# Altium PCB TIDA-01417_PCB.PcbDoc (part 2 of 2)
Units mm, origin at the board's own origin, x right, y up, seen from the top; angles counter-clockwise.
Board outline 64 x 64 mm, 2 copper layers (Top Layer, Bottom Layer), stack 1.575 mm thick; 69 components, 44 nets, 174 pads, 84 vias.
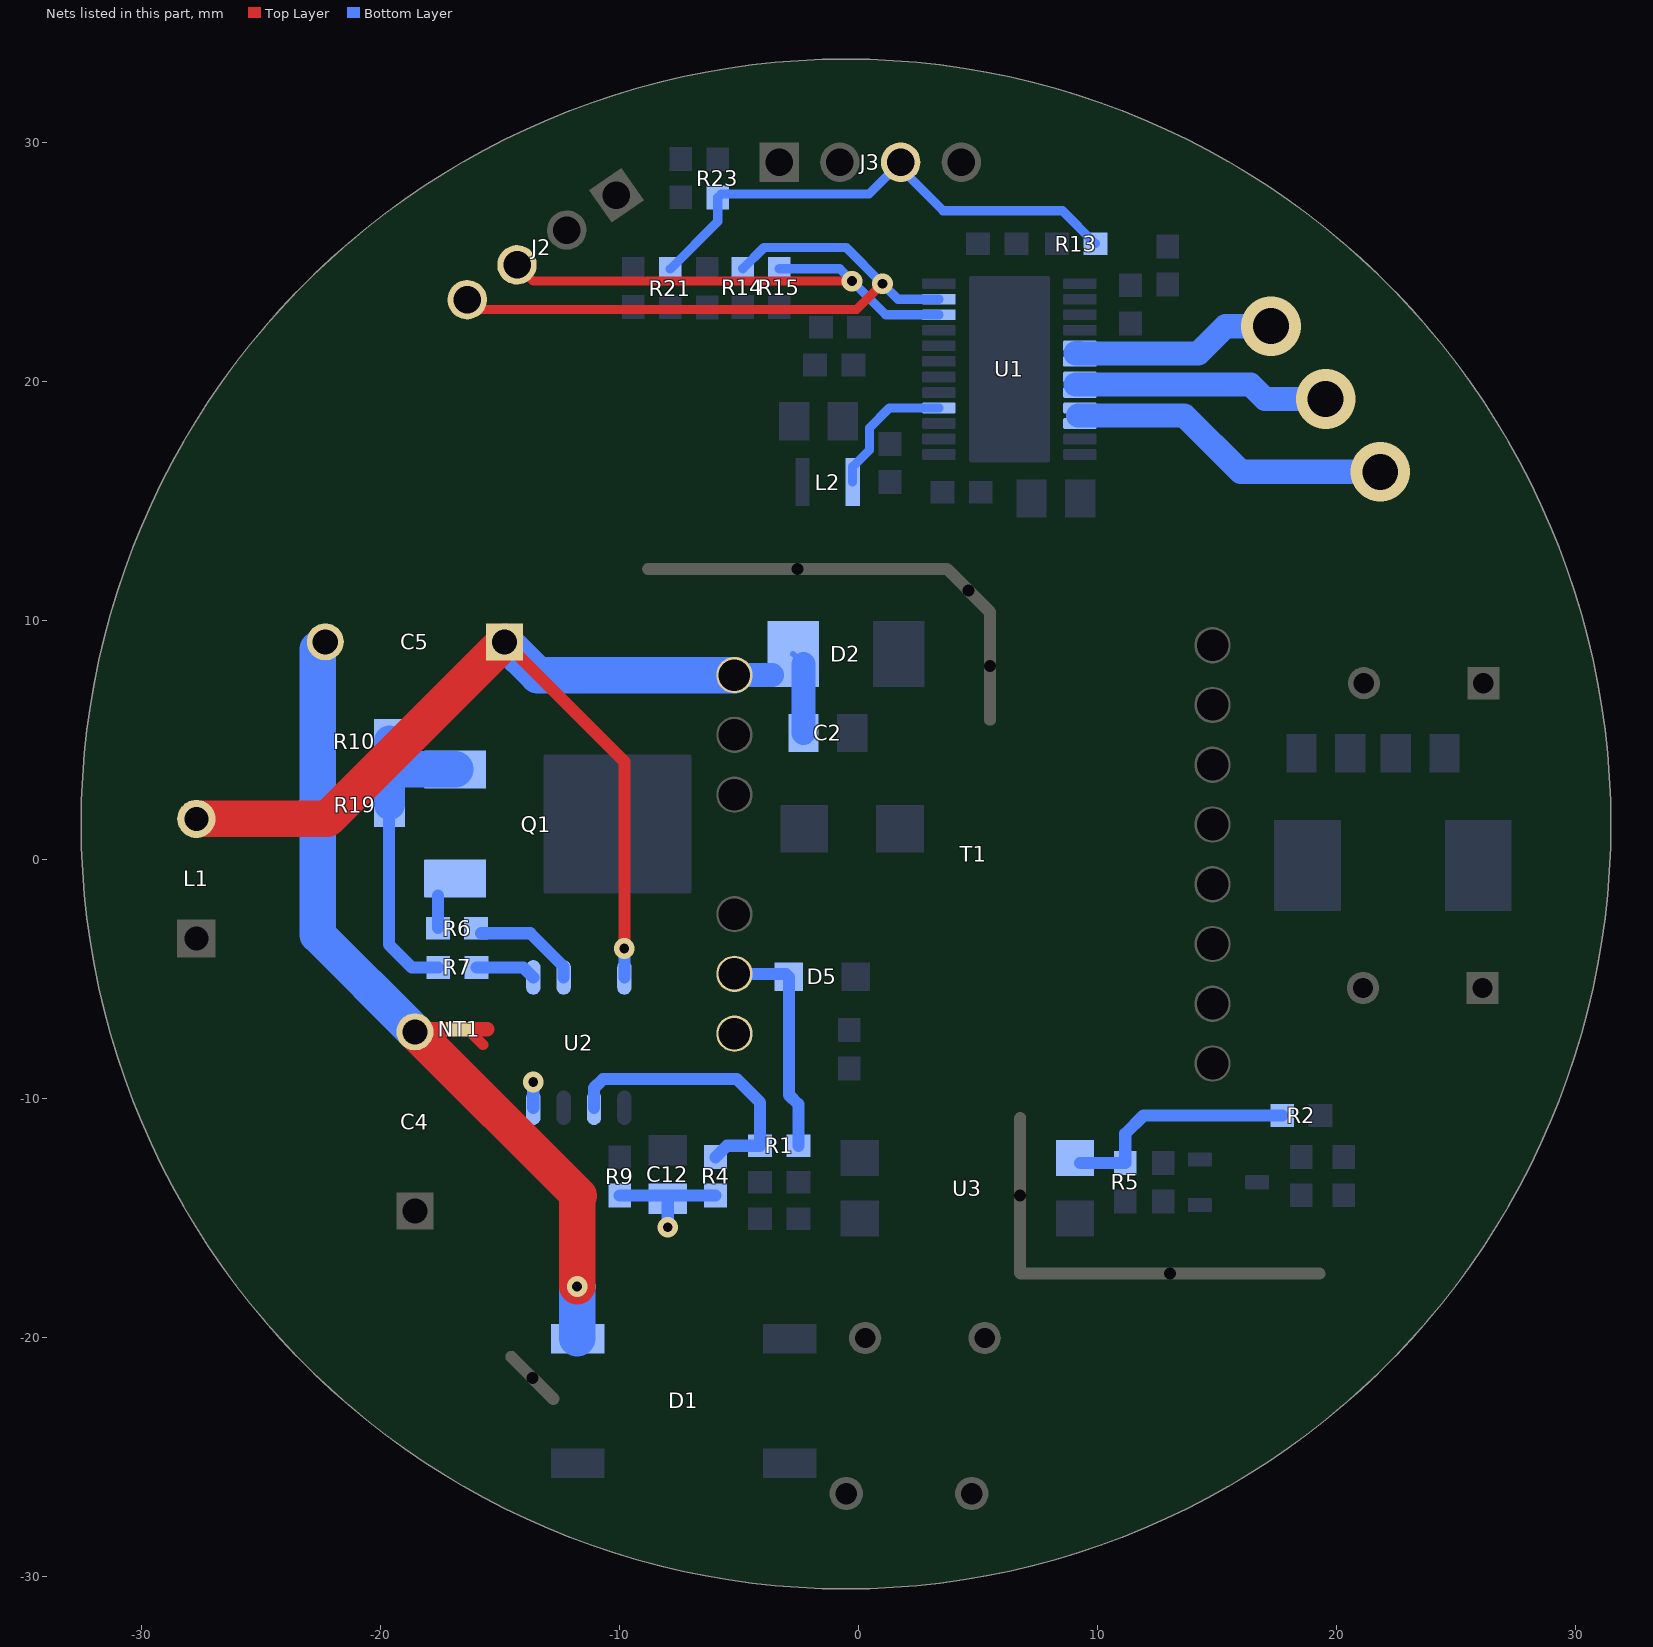
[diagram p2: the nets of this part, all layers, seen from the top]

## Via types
v1: diameter 0.864, hole 0.406, Top Layer to Bottom Layer, 58 vias
v2: diameter 0.5, hole 0.2, Top Layer to Bottom Layer, 15 vias
v3: diameter 0.5, hole 0.2, Top Layer to Bottom Layer, tented both sides, 6 vias
v4: diameter 2.5, hole 1.5, Top Layer to Bottom Layer, 5 vias

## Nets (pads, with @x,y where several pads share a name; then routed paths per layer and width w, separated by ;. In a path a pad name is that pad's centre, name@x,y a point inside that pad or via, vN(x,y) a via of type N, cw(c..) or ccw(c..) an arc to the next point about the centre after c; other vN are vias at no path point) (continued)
NetD5_2: D5.2 R1.2 T1.5 | length 9.7
  Bottom Layer w0.508: T1.5@-5.508,-4.784 T1.5@-5.174,-4.784 D5.2@-3.025,-4.784 ; D5.2@-2.89,-4.919 -2.89,-9.848 -2.502,-10.236 R1.2@-2.502,-11.976
NetL2_1: L2.1 U1.4 | length 5.8
  Bottom Layer w0.381: L2.1@-0.23,15.789 -0.23,16.431 0.468,17.128 0.468,18.049 1.31,18.89 U1.4@3.38,18.89
NetQ1_1: Q1.1 R6.2 | length 1.4
  Bottom Layer w0.508: R6.2@-17.58,-2.872 Q1.1@-17.58,-1.512
NetQ1_3: Q1.3 R7.2 R10.2 R19.2 | length 13.5
  Bottom Layer w0.508: R19.2@-19.632,2.31 -19.632,-3.557 -18.674,-4.515 R7.2@-17.565,-4.515
  Bottom Layer w1.3: R19.2@-19.606,2.31 R10.2@-19.606,4.957
  Bottom Layer w1.524: -19.361,3.771 Q1.3@-16.851,3.771
NetR1_1: R1.1 R4.2 U2.2 | length 12.2
  Bottom Layer w0.508: U2.2@-11.049,-10.383 -11.049,-9.563 -10.668,-9.182 -5.08,-9.182 -4.102,-10.16 R1.1@-4.102,-11.976 -5.488,-11.976 R4.2@-5.964,-12.453
NetR2_1: R2.1 R5.2 U3.1 | length 10
  Bottom Layer w0.508: U3.1@9.288,-12.7 R5.2@11.176,-12.7 11.176,-11.468 11.938,-10.706 R2.1@17.742,-10.706
NetR6_1: R6.1 U2.6 | length 4.5
  Bottom Layer w0.508: R6.1@-15.766,-3.086 -13.716,-3.086 -12.319,-4.483 U2.6@-12.319,-4.933
NetR7_1: R7.1 U2.5 | length 2.5
  Bottom Layer w0.508: R7.1@-15.965,-4.515 -14.007,-4.515 U2.5@-13.589,-4.933
PGND: C4.2 C5.2 D1.2 NT1.2 R10.1 R19.1 | length 34.9
  Top Layer w0.25: C4.2@-18.542,-7.21 C4.2@-18.534,-7.218
  Top Layer w0.6: C4.2@-18.42,-7.104 NT1.2@-16.935,-7.104
  Top Layer w1.524: C4.2@-18.534,-7.218 -11.684,-14.068 -11.758,-14.143 v1(-11.758,-17.86)
  Bottom Layer w1.524: C5.2@-22.606,8.792 -22.606,-3.146 C4.2@-18.542,-7.21 ; D1.2@-11.758,-20.022 v1(-11.758,-17.86)
SCL: J2.3 R15.2 U1.10 | length 21.8
  Top Layer w0.381: J2.3@-14.271,24.877 -13.594,24.199 v1(-0.254,24.199)
  Bottom Layer w0.381: R15.2@-3.302,24.714 -0.769,24.714 v1(-0.254,24.199) 1.155,22.79 U1.10@3.38,22.79
SDA: J2.4 R14.2 U1.11 | length 26.9
  Top Layer w0.381: J2.4@-15.937,23.005 -0.071,23.005 v1(1.016,24.092)
  Bottom Layer w0.381: R14.2@-4.826,24.714 -4.826,24.718 -3.939,25.605 -0.497,25.605 v1(1.016,24.092) 1.667,23.44 U1.11@3.38,23.44
SGND: C12.1 NT1.1 R4.1 R9.1 T1.6 U2.4 | length 7.9
  Top Layer w0.2: NT1.1@-16.229,-7.39 -16.166,-7.453 ; NT1.1@-16.229,-7.22 NT1.1@-16.144,-7.305
  Top Layer w0.45: -16.081,-7.368 -15.697,-7.751
  Top Layer w0.508: v1@-7.974,-15.393 v1(-7.965,-15.383)
  Top Layer w0.6: NT1.1@-16.427,-7.104 -15.519,-7.104
  Bottom Layer w0.508: U2.4@-13.589,-10.383 v1(-13.589,-9.309) ; R9.1@-9.974,-14.054 R4.1@-5.966,-14.054 ; v1(-7.965,-15.383) C12.1@-7.965,-14.192
SPEED: J3.3 R13.1 R21.1 R23.2 | length 21.5
  Bottom Layer w0.381: R21.1@-7.863,24.702 -5.875,26.69 R23.2@-5.875,27.69 -5.726,27.84 0.446,27.84 J3.3@1.778,29.172 ; J3.3@1.778,28.918 3.556,27.14 8.549,27.14 R13.1@9.924,25.765
U: U1.17 U1.18 | length 8.6
  Bottom Layer w1.016: 9.099,21.176 9.279,21.175 ; 9.28,21.175 13.595,21.171 14.224,21.171 15.367,22.314 v4(17.272,22.314)
V: U1.19 U1.20 | length 10.7
  Bottom Layer w1.016: 9.104,19.872 16.412,19.872 17.018,19.266 v4(19.558,19.266)
VDCBUS: C2.1 C5.1 D2.2 L1.2 T1.1 U2.8 | length 47.3
  Top Layer w0.508: C5.1@-14.792,9.106 -9.779,4.093 v1(-9.779,-3.721)
  Top Layer w1.524: L1.2@-27.686,1.7 -22.198,1.7 C5.1@-14.792,9.106
  Bottom Layer w0.254: D2.2@-2.718,8.598 D2.2@-2.286,8.166
  Bottom Layer w0.508: U2.8@-9.779,-4.933 v1(-9.779,-3.721)
  Bottom Layer w1.016: T1.1@-5.174,7.716 D2.2@-3.6,7.716 ; C2.1@-2.286,5.296 D2.2@-2.286,8.166
  Bottom Layer w1.524: C5.1@-14.792,9.106 -13.402,7.716 T1.1@-5.174,7.716
W: U1.21 U1.22 | length 13.6
  Bottom Layer w1.016: 9.203,18.573 13.647,18.573 16.003,16.218 v4(21.844,16.218)
pads on no net: T1.2 T1.4 T1.7 T1.10 T1.11 T1.14 U1.25@6.329,20.515

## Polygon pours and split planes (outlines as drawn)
GND on Bottom Layer "Bottom Layer-No Net 3" (solid, remove dead copper, pour order 12): -22.352,24.6 -17.272,19.52 -9.652,19.52 -3.297,13.165 4.323,13.165 5.588,11.9 10.668,11.9 13.208,9.36 13.208,-8.42 10.668,-10.96 10.668,-15.732 28.756,-15.732 33.528,-10.96 33.528,11.9 10.668,34.76 -12.192,34.76
NetC17_1 on Bottom Layer "Bottom Layer-No Net" (solid, pour order 4): 13.97,-2.578 13.462,-3.086 13.462,-6.642 13.716,-6.896 13.97,-7.15 16.002,-7.15 16.256,-6.896 16.256,-5.88 19.812,-2.324 20.32,-2.324 20.828,-1.816 20.828,2.502 20.574,2.756 17.272,2.756 16.764,2.248 16.51,1.994 16.51,-1.562 15.494,-2.578
NetC2_2 on Bottom Layer "Top Layer-No Net" (solid, remove dead copper, pour order 2): -0.889,6.185 -0.889,4.534 -0.889,4.153 0.254,4.153 0.457,3.95 0.457,0.648 0.686,0.419 3.302,0.419 4.343,1.461 4.572,1.689 4.572,9.842 4.166,10.249 1.702,10.249 0.889,10.249 0.635,9.995 0.635,8.522 0.635,6.617 0.203,6.185
+24V on Bottom Layer "Bottom Layer-No Net 1" (solid, pour order 8): 23.876,6.82 25.4,8.344 29.718,8.344 30.988,7.074 30.988,0.978 30.988,-3.848 29.718,-5.118 29.718,-5.372 29.718,-6.134 29.21,-6.642 28.702,-7.15 25.146,-7.15 23.876,-5.88 23.876,6.82
PGND on Bottom Layer "BOTTOM_LAYER_PGND_P024" (solid, remove dead copper, pour order 24): -19.05,-6.096 -18.034,-6.096 -17.526,-6.604 -17.526,-7.62 -17.526,-7.874 -18.034,-8.382 -18.796,-8.382 -19.05,-8.382 -19.558,-7.874 -19.558,-6.604 -19.05,-6.096
SGND on Top Layer "Top Layer-No Net 4" (solid, pour order 22): -6.096,-5.838 1.27,-5.838 1.27,-15.532 0.762,-16.04 -8.006,-16.04 -16.463,-7.583 -16.463,-6.807 -13.236,-6.807 -11.311,-8.928 -7.112,-8.928 -6.096,-7.912
GND on Top Layer "Top Layer-No Net 3" (solid, pour order 18): -22.352,24.6 -17.272,19.52 -9.652,19.52 -3.266,13.134 4.354,13.134 5.588,11.9 10.668,11.9 13.208,9.36 13.208,9.331 13.208,-8.166 10.668,-10.706 10.668,-15.788 26.668,-15.788 32.766,-9.69 33.528,-8.928 33.528,9.36 33.528,14.44 20.828,27.14 14.478,33.49 -9.652,33.49 -13.462,33.49
+24V on Top Layer "Top Layer-No Net 2" (solid, pour order 16): 23.876,6.82 25.4,8.344 28.94,8.344 31.496,8.344 30.734,7.582 30.734,-7.15 25.146,-7.15 23.876,-5.88 23.876,6.82
NetC17_1 on Top Layer "Top Layer-No Net 1" (solid, pour order 14): 13.462,-3.086 13.97,-2.578 15.494,-2.578 16.51,-1.562 16.51,1.994 17.272,2.756 20.574,2.756 20.828,2.502 20.828,-1.816 20.32,-2.324 19.812,-2.324 16.256,-5.88 16.256,-6.896 16.027,-7.125 13.945,-7.125 13.462,-6.642 13.462,-3.086
PGND on Top Layer "TOP_LAYER_PGND_P030" (solid, remove dead copper, pour order 30): -18.034,-6.096 -17.526,-6.604 -17.526,-7.874 -18.034,-8.382 -19.05,-8.382 -19.558,-7.874 -19.558,-6.858 -19.558,-6.604 -19.05,-6.096 -18.034,-6.096

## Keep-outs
Keep-Out Layer:
  circle w0.254: c-0.508,1.494 r32.064
  text ".Layer_Name" at -35.636,-60.706 h1.52

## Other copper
Top Layer:
  text ".Layer_Name" at -35.636,-60.706 h1.52
Bottom Layer:
  text ".Layer_Name" at -35.636,-60.706 h1.52

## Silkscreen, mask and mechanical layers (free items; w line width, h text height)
Top Overlay:
  text "GND" at -12.402,30.461 h0.76 r305
  text "FG" at -14.094,28.51 h0.76 r305
  text "SCL" at -16.587,27.541 h0.76 r305
  text "GND" at -3.81,27.432 h0.76 r270
  text "FG" at -1.27,27.432 h0.76 r270
  text "SPEED" at 1.27,27.432 h0.76 r270
  text "DIR" at 3.996,27.366 h0.76 r270
  text "SDA" at -18.693,26.146 h0.76 r305
  text "W   V   U" at 21.082,13.716 h3 r127
  text "TIDA-01417" at -7.142,-14.464 h2.75
  text "N" at 15.543,-20.563 h3 r90
  text "L" at 10.308,-23.461 h3 r90
  text ".Layer_Name" at -35.636,-60.706 h1.52
Bottom Overlay:
  text ".Layer_Name" at -35.636,-60.706 h1.52
Top Paste:
  text ".Layer_Name" at -35.636,-60.706 h1.52
Bottom Paste:
  text ".Layer_Name" at -35.636,-60.706 h1.52
Top Solder:
  text ".Layer_Name" at -35.636,-60.706 h1.52
  text ".Layer_Name" at -35.636,-60.706 h1.52
Bottom Solder:
  text ".Layer_Name" at -35.636,-60.706 h1.52
Drill Guide:
  text ".Layer_Name" at -35.636,-60.706 h1.52
M3 3D STEP Top:
  text ".Layer_Name" at -35.636,-60.706 h1.52
M4 3D STEP Bottom:
  text ".Layer_Name" at -35.636,-60.706 h1.52
M5 Assembly Top:
  lines w0.254: -57.709,-62.526 109.931,-62.526 ; -57.709,-57.362 109.982,-57.362 ; -57.709,-52.197 -57.709,-67.691 44.018,-67.691 109.982,-67.691 109.982,-52.197 -57.696,-52.197 -57.696,-67.691 -17.678,-67.691 ; 4.902,-67.691 4.902,-52.197 ; 37.084,-57.362 37.084,-52.197 ; 58.42,-57.362 58.42,-52.197 ; 74.219,-67.856 74.219,-62.704
  text "COMPONENTS MARKED 'DNP' SHOULD NOT BE POPULATED." at -20.993,-46.99 h1.52
  text "ASSEMBLY VARIANT:" at -21.006,-49.924 h1.52
  text ".VariantName" at 5.309,-49.924 h1.52
  text "PCB VIEWED FROM TOP SIDE" at -56.096,-55.554 h1.52
  text "BOARD #:" at 6.807,-55.554 h1.52
  text ".PRJ_Number" at 20.663,-55.554 h1.52
  text "REV:" at 42.113,-55.554 h1.52
  text ".PCB_Rev" at 49.517,-55.554 h1.52
  text "SVN REV:" at 63.398,-55.554 h1.52
  text ".VersionControl_RevNumber" at 76.251,-55.554 h1.52
  text "TID #:" at 6.807,-60.719 h1.52
  text ".TID" at 20.663,-60.719 h1.52
  text "PLOT NAME =" at -56.096,-65.934 h1.52
  text ".plot_File_Name" at -35.636,-65.934 h1.52
  text "GENERATED    :" at 6.858,-65.934 h1.52
  text ".Print_Date" at 28.943,-65.934 h1.52
  text ".Print_Time" at 47.46,-65.934 h1.52
  text "TEXAS INSTRUMENTS" at 79.578,-65.934 h1.52
M6 Assembly Bottom:
  lines w0.254: -57.721,-57.374 109.969,-57.374 ; -57.671,-62.539 109.969,-62.539 ; -21.958,-67.869 -21.958,-62.717 ; -6.159,-57.374 -6.159,-52.21 ; 15.176,-57.374 15.176,-52.21 ; 47.358,-67.704 47.358,-52.21 ; 69.939,-67.704 109.957,-67.704 109.957,-52.21 -57.721,-52.21 -57.721,-67.704 8.242,-67.704 109.969,-67.704 109.969,-52.21
  text "COMPONENTS MARKED 'DNP' SHOULD NOT BE POPULATED." at 104.699,-46.977 h1.52
  text ".VariantName" at 78.181,-49.924 h1.52
  text "ASSEMBLY VARIANT:" at 104.572,-49.924 h1.52
  text ".VersionControl_RevNumber" at -23.99,-55.567 h1.52
  text "SVN REV:" at -11.138,-55.567 h1.52
  text ".PCB_Rev" at 2.743,-55.567 h1.52
  text "REV:" at 10.147,-55.567 h1.52
  text ".PRJ_Number" at 31.598,-55.567 h1.52
  text "BOARD #:" at 45.453,-55.567 h1.52
  text "PCB VIEWED FROM BOTTOM SIDE" at 108.356,-55.567 h1.52
  text ".TID" at 31.598,-60.731 h1.52
  text "TID #:" at 45.453,-60.731 h1.52
  text "TEXAS INSTRUMENTS" at -27.318,-65.947 h1.52
  text ".Print_Time" at 4.801,-65.947 h1.52
  text ".Print_Date" at 23.317,-65.947 h1.52
  text "GENERATED    :" at 45.402,-65.947 h1.52
  text ".plot_File_Name" at 87.897,-65.947 h1.52
  text "PLOT NAME =" at 108.356,-65.947 h1.52
M9 Title Sheet:
  drawing of 57 lines, arcs and shapes, not listed
  text "1" at -31.5,165.227 h1.78
  text "2" at 31.89,165.227 h1.78
  text "3" at 95.119,165.227 h1.78
  text "4" at 158.788,165.227 h1.78
  text "5" at 222.263,165.227 h1.78
  text "6" at 285.89,165.227 h1.78
  text "A" at -60.871,136.195 h1.78
  text "A" at 315.049,136.195 h1.78
  text "B" at -60.871,75.743 h1.78
  text "B" at 315.049,75.743 h1.78
  text "C" at -60.871,15.418 h1.78
  text "C" at 315.049,15.418 h1.78
  text "PROJECT TITLE:" at 237.833,-31.852 h1.14
  text ".PRJ_Title" at 239.103,-35.238 h1.78
  text "DESIGNED FOR:" at 237.833,-39.497 h1.14
  text ".PRJ_Customer" at 239.103,-43.053 h1.78
  text "D" at -60.871,-44.78 h1.78
  text "D" at 315.049,-44.78 h1.78
  text "FILE NAME:" at 237.833,-47.117 h1.14
  text ".PCB_File_Name_No_Path" at 239.103,-50.165 h1.78
  text "Texas Instruments (TI) and/or its licensors do not warrant the accuracy or completeness of this specification" at 111.608,-54.276 h1.14
  text "ENGINEER:" at 237.833,-54.483 h1.14
  text "LAYOUT BY:" at 276.06,-54.483 h1.14
  text "or any information contained therein. TI and/or its licensors do not warrant that this design will meet" at 110.465,-57.137 h1.14
  text ".PRJ_Engineer" at 239.103,-58.42 h1.78
  text ".PCB_Layout" at 277.343,-58.42 h1.78
  text "the specifications, will be suitable for your application or fit for any particular purpose, or will operate in" at 110.465,-59.999 h1.14
  text ".Layer_Name" at -35.636,-60.706 h1.52
  text "ALTIUM DESIGNER VERSION:" at 276.06,-62.357 h1.14
  text "an implementation. TI and/or its licensors do not warrant that the design is production worthy. You should" at 110.465,-62.861 h1.14
  text "completely validate and test your design implementation to confirm the system functionality for your application." at 111.608,-65.722 h1.14
  text ".print_Scale" at 239.103,-65.744 h1.78
  text ".Application_BuildNumber" at 277.343,-65.744 h1.78
  text "1" at -31.5,-70.993 h1.78
  text "2" at 31.89,-70.993 h1.78
  text "3" at 95.119,-70.993 h1.78
  text "4" at 158.788,-70.993 h1.78
  text "5" at 222.263,-70.993 h1.78
  text "6" at 285.89,-70.993 h1.78
M10 Fab Notes:
  drawing of 173 lines, arcs and shapes, not listed
  text "DESIGN INFORMATION" at 264.11,118.605 h1.52
  text "MIN. TRACK WIDTH:" at 247.738,114.033 h1.52
  text "8" at 275.582,114.033 h1.52
  text "MIL" at 279.513,114.033 h1.52
  text "MIN. CLEARANCE:" at 247.738,110.681 h1.52
  text "0.2" at 274.058,110.681 h1.52
  text "mm" at 279.513,110.681 h1.52
  text "MIN. VIA PAD SIZE:" at 247.738,107.328 h1.52
  text "24" at 274.821,107.328 h1.52
  text "MIL" at 279.513,107.328 h1.52
  text "0.05mm (2MIL)" at 265.391,103.728 h1.52
  text "MINIMUM ANNULAR RING" at 239.375,103.619 h1.52
  text "EXTERNAL" at 283.374,103.619 h1.52
  text "PER" at 244.455,100.622 h1.52
  text "IPC-D-275 CLASS 2 LEVEL C" at 250.043,100.622 h1.52
  text "MIL, HOLES" at 287.844,97.77 h1.52
  text "+/-" at 277.876,97.752 h1.52
  text "+/-" at 299.568,97.752 h1.52
  text "REGISTRATION TOLERANCES:" at 239.375,97.625 h1.52
  text "METAL" at 269.85,97.625 h1.52
  text "5" at 284.485,97.625 h1.52
  text "3" at 305.643,97.625 h1.52
  text "MIL" at 308.596,97.625 h1.52
  text "+/-" at 299.568,94.755 h1.52
  text "HOLE SIZE TOLERANCE (UNLESS OTHERWISE SPECIFIED):" at 239.375,94.628 h1.52
  text "3" at 305.643,94.628 h1.52
  text "MIL" at 308.596,94.628 h1.52
  text "MATERIAL:" at 237.476,89.307 h1.52
  text "FR-4 High Tg" at 262.532,85.743 h1.52
  text "FR-408" at 248.17,85.525 h1.52
  text "OTHER" at 285.965,85.525 h1.52
  text "X" at 258.597,85.433 h1.52
  text "62 MIL (1.6mm) +/-10%" at 256.3,81.392 h1.52
  text "THICKNESS:" at 239.375,81.284 h1.52
  text "X" at 253.045,81.284 h1.52
  text "OTHER" at 288.937,81.284 h1.52
  text "TOLERANCE:" at 239.375,77.27 h1.52
  text "X" at 260.694,77.27 h1.52
  text "ANSI IPC-6012 TYPE 3 CLASS 2" at 265.442,77.27 h1.52
  text "OTHER +/-" at 265.442,73.308 h1.52
  text "BOW & TWIST:" at 239.375,69.32 h1.52
  text "X" at 260.694,69.32 h1.52
  text "ANSI IPC-6012 TYPE 3 CLASS 2" at 265.442,69.32 h1.52
  text "OTHER +/-" at 265.442,65.294 h1.52
  text "DRILLING:" at 237.476,61.776 h1.52
  text "REFERENCE:" at 239.375,58.805 h1.52
  text "X" at 255.84,58.805 h1.52
  text "AS SHOWN" at 260.59,58.805 h1.52
  text "X" at 278.726,58.805 h1.52
  text "NC_DRILL FILES" at 282.206,58.805 h1.52
  text "PTH COPPER THICKNESS:" at 239.375,54.791 h1.52
  text "X" at 268.083,54.791 h1.52
  text "20-30 um" at 271.563,54.791 h1.52
  text "OTHER" at 289.775,54.791 h1.52
  text "BOARD FINISH:" at 237.476,50.753 h1.52
  text "SILKSCREEN:" at 241.419,47.756 h1.52
  text "X" at 265.518,47.756 h1.52
  text "TOP" at 268.718,47.756 h1.52
  text "X" at 278.472,47.756 h1.52
  text "BOTTOM" at 281.698,47.756 h1.52
  text "SILKSCREEN COLOR:" at 241.419,43.514 h1.52
  text "X" at 265.491,43.514 h1.52
  text "WHITE" at 268.718,43.514 h1.52
  text "OTHER" at 281.698,43.514 h1.52
  text "X" at 268.819,39.47 h1.52
  text "GREEN" at 272.046,39.47 h1.52
  text "OTHER" at 287.743,39.47 h1.52
  text "SOLDER RESIST COLOR:" at 241.419,39.196 h1.52
  text "X" at 268.819,35.152 h1.52
  text "MATTE" at 272.046,35.152 h1.52
  text "SEMI-GLOSS" at 287.731,35.136 h1.52
  text "IMMERSION GOLD (ENIG)" at 264.426,30.364 h1.52
  text "ENEPIG" at 298.399,30.28 h1.52
  text "SURFACE FINISH:" at 237.476,30.255 h1.52
  text "X" at 259.677,30.255 h1.52
  text "IMM. TIN/SILVER OR EQUIV" at 245.847,26.267 h1.52
  text "OTHER" at 282.206,26.267 h1.52
  text "ARRAY/PANEL:" at 237.476,21.721 h1.52
  text "CUT AND TRIM PER M1 BOARD OUTLINE" at 264.426,21.612 h1.52
  text "N.C. ROUTE" at 264.426,17.758 h1.52
  text "X" at 281.672,17.758 h1.52
  text "V. SCORE" at 286.422,17.758 h1.52
  text "CERTIFICATION:" at 237.476,14.278 h1.52
  text "MATERIALS AND WORKMANSHIP FOR ALL PCBS" at 255.891,14.278 h1.52
  text "TO MEET OR EXCEED THE REQUIREMENTS OF:" at 255.891,11.789 h1.52
  text "X" at 246.404,8.322 h1.52
  text "ANSI IPC-A-600F CLASS ->" at 249.935,8.322 h1.52
  text "X" at 291.567,8.322 h1.52
  text "2" at 294.588,8.322 h1.52
  text "1" at 286.587,8.284 h1.52
  text "3" at 303.58,8.284 h1.52
  text "X" at 267.081,4.271 h1.52
  text "RoHS" at 270.56,4.271 h1.52
  text "OTHER" at 286.928,4.271 h1.52
  text "PER ORDER" at 297.013,4.271 h1.52
  text "ALL BOARDS MUST MEET OR EXCEED UL94-V0 REQUIREMENTS." at 238.176,0.064 h1.52
  text "PCB MUST BEAR THE UL94V-0 UL REGISTERED MATERIAL ID NUMBER" at 238.176,-2.984 h1.52
  text "ADDITIONAL REQUIREMENTS:" at 237.476,-7.388 h1.52
  text "MICROSECTION:" at 239.375,-10.309 h1.52
  text "YES" at 262.381,-10.309 h1.52
  text "REQUIRED" at 284.263,-14.275 h1.52
  text "BARE BOARD ELEC. TEST:" at 239.375,-14.347 h1.52
  text "NONE" at 272.541,-14.347 h1.52
  text "X" at 281.037,-14.347 h1.52
  text "PER ORDER" at 299.3,-14.347 h1.52
  text ".Layer_Name" at -35.636,-60.706 h1.52
M11 Gerber Information:
  lines w0.254: -57.709,-62.526 109.931,-62.526 ; -57.709,-57.362 109.982,-57.362 ; -57.709,-52.197 -57.709,-67.691 44.018,-67.691 109.982,-67.691 109.982,-52.197 -57.696,-52.197 -57.696,-67.691 -17.678,-67.691 ; 4.902,-67.691 4.902,-52.197 ; 37.084,-57.362 37.084,-52.197 ; 58.42,-57.362 58.42,-52.197 ; 74.219,-67.856 74.219,-62.704
  text "ALL ARTWORK VIEWED FROM TOP SIDE" at -56.096,-55.554 h1.52
  text "BOARD #:" at 6.807,-55.554 h1.52
  text ".PRJ_Number" at 20.663,-55.554 h1.52
  text "REV:" at 42.113,-55.554 h1.52
  text ".PCB_Rev" at 49.517,-55.554 h1.52
  text "SVN REV:" at 63.398,-55.554 h1.52
  text ".VersionControl_RevNumber" at 76.251,-55.554 h1.52
  text "LAYER NAME =" at -56.096,-60.706 h1.52
  text "TID #:" at 6.807,-60.719 h1.52
  text ".TID" at 20.663,-60.719 h1.52
  text "PLOT NAME =" at -56.096,-65.934 h1.52
  text ".plot_File_Name" at -35.636,-65.934 h1.52
  text "GENERATED    :" at 6.858,-65.934 h1.52
  text ".Print_Date" at 28.943,-65.934 h1.52
  text ".Print_Time" at 47.46,-65.934 h1.52
  text "TEXAS INSTRUMENTS" at 79.578,-65.934 h1.52
M12 Stackup:
  drawing of 191 lines, arcs and shapes, not listed
  text "Layer" at 198.383,159.982 h1.52
  text "Name" at 208.794,159.982 h1.52
  text "Material" at 232.41,159.982 h1.52
  text "Thickness" at 254.248,159.982 h1.52
  text "Constant" at 270.754,159.982 h1.52
  text "Board Layer Stack" at 285.228,159.982 h1.52
  text "1" at 198.383,156.934 h1.52
  text "Top Overlay" at 208.794,156.934 h1.52
  text "2" at 198.383,153.886 h1.52
  text "Top Solder" at 208.794,153.886 h1.52
  text "Solder Resist" at 232.41,153.886 h1.52
  text "0.40mil" at 254.248,153.886 h1.52
  text "3.5" at 270.754,153.886 h1.52
  text "3" at 198.383,150.838 h1.52
  text "Top Layer" at 208.794,150.838 h1.52
  text "Copper" at 232.41,150.838 h1.52
  text "1.40mil" at 254.248,150.838 h1.52
  text "4" at 198.383,147.79 h1.52
  text "Dielectric1" at 208.794,147.79 h1.52
  text "FR-4" at 232.41,147.79 h1.52
  text "59.20mil" at 254.248,147.79 h1.52
  text "4.8" at 270.754,147.79 h1.52
  text "5" at 198.383,144.742 h1.52
  text "Bottom Layer" at 208.794,144.742 h1.52
  text "Copper" at 232.41,144.742 h1.52
  text "1.40mil" at 254.248,144.742 h1.52
  text "6" at 198.383,141.694 h1.52
  text "Bottom Solder" at 208.794,141.694 h1.52
  text "Solder Resist" at 232.41,141.694 h1.52
  text "0.40mil" at 254.248,141.694 h1.52
  text "3.5" at 270.754,141.694 h1.52
  text "7" at 198.383,138.646 h1.52
  text "Bottom Overlay" at 208.794,138.646 h1.52
  text ".Layer_Name" at -35.636,-60.706 h1.52
M13 Component Bodies Top:
  text ".Layer_Name" at -35.636,-60.706 h1.52
M14 Component Bodies Bottom:
  text ".Layer_Name" at -35.636,-60.706 h1.52
M15 Courtyards Top:
  text ".Layer_Name" at -35.636,-60.706 h1.52
M16 Courtyards Bottom:
  text ".Layer_Name" at -35.636,-60.706 h1.52
Drill Drawing:
  drawing of 156 lines, arcs and shapes, not listed
  text "Symbol" at 85.491,47.094 h1.83
  text "Quantity" at 92.749,47.094 h1.83
  text "Finished Hole Size" at 100.805,47.094 h1.83
  text "Plated" at 116.597,47.094 h1.83
  text "Hole Type" at 122.803,47.094 h1.83
  text "Drill Layer Pair" at 131.956,47.094 h1.83
  text "Hole Tolerance" at 149.977,47.094 h1.83
  text "21" at 92.749,44.563 h1.52
  text "7.87mil (0.200mm)" at 100.805,44.563 h1.52
  text "PTH" at 116.597,44.563 h1.52
  text "Round" at 122.803,44.563 h1.52
  text "Top Layer - Bottom Layer" at 131.956,44.563 h1.52
  text "58" at 92.749,42.033 h1.52
  text "16.00mil (0.406mm)" at 100.805,42.033 h1.52
  text "PTH" at 116.597,42.033 h1.52
  text "Round" at 122.803,42.033 h1.52
  text "Top Layer - Bottom Layer" at 131.956,42.033 h1.52
  text "6" at 92.749,39.503 h1.52
  text "33.46mil (0.850mm)" at 100.805,39.503 h1.52
  text "PTH" at 116.597,39.503 h1.52
  text "Round" at 122.803,39.503 h1.52
  text "Top Layer - Bottom Layer" at 131.956,39.503 h1.52
  text "2" at 92.749,36.972 h1.52
  text "35.43mil (0.900mm)" at 100.805,36.972 h1.52
  text "PTH" at 116.597,36.972 h1.52
  text "Round" at 122.803,36.972 h1.52
  text "Top Layer - Bottom Layer" at 131.956,36.972 h1.52
  text "2" at 92.749,34.442 h1.52
  text "39.37mil (1.000mm)" at 100.805,34.442 h1.52
  text "PTH" at 116.597,34.442 h1.52
  text "Round" at 122.803,34.442 h1.52
  text "Top Layer - Bottom Layer" at 131.956,34.442 h1.52
  text "4" at 92.749,31.911 h1.52
  text "41.34mil (1.050mm)" at 100.805,31.911 h1.52
  text "PTH" at 116.597,31.911 h1.52
  text "Round" at 122.803,31.911 h1.52
  text "Top Layer - Bottom Layer" at 131.956,31.911 h1.52
  text "8" at 92.749,29.381 h1.52
  text "45.28mil (1.150mm)" at 100.805,29.381 h1.52
  text "PTH" at 116.597,29.381 h1.52
  text "Round" at 122.803,29.381 h1.52
  text "Top Layer - Bottom Layer" at 131.956,29.381 h1.52
  text "14" at 92.749,26.851 h1.52
  text "51.97mil (1.320mm)" at 100.805,26.851 h1.52
  text "PTH" at 116.597,26.851 h1.52
  text "Round" at 122.803,26.851 h1.52
  text "Top Layer - Bottom Layer" at 131.956,26.851 h1.52
  text "5" at 92.749,24.32 h1.52
  text "59.06mil (1.500mm)" at 100.805,24.32 h1.52
  text "PTH" at 116.597,24.32 h1.52
  text "Round" at 122.803,24.32 h1.52
  text "Top Layer - Bottom Layer" at 131.956,24.32 h1.52
  text "2" at 92.749,21.79 h1.52
  text "20.00mil (0.508mm)" at 100.805,21.79 h1.52
  text "NPTH" at 116.597,21.79 h1.52
  text "Slot" at 122.803,21.79 h1.52
  text "Top Layer - Bottom Layer" at 131.956,21.79 h1.52
  text "1" at 92.749,19.259 h1.52
  text "20.00mil (0.508mm)" at 100.805,19.259 h1.52
  text "NPTH" at 116.597,19.259 h1.52
  text "Slot" at 122.803,19.259 h1.52
  text "Top Layer - Bottom Layer" at 131.956,19.259 h1.52
  text "1" at 92.749,16.729 h1.52
  text "20.00mil (0.508mm)" at 100.805,16.729 h1.52
  text "NPTH" at 116.597,16.729 h1.52
  text "Slot" at 122.803,16.729 h1.52
  text "Top Layer - Bottom Layer" at 131.956,16.729 h1.52
  text "2" at 92.749,14.198 h1.52
  text "20.00mil (0.508mm)" at 100.805,14.198 h1.52
  text "NPTH" at 116.597,14.198 h1.52
  text "Slot" at 122.803,14.198 h1.52
  text "Top Layer - Bottom Layer" at 131.956,14.198 h1.52
  text "126 Total" at 92.749,11.668 h1.52
  text "Slot definitions :" at 85.491,9.646 h1.52
  text "Routed Path Length" at 96.751,9.646 h1.52
  text "= Calculated from tool start centre position to tool end centre position." at 110.272,9.646 h1.52
  text "Hole Length" at 96.751,8.383 h1.52
  text "= Routed Path Length + Tool Size = Slot length as defined in the PCB layout" at 105.197,8.383 h1.52
  text ".Layer_Name" at -35.636,-60.706 h1.52
M17 Embedded Cavity:
  text ".Layer_Name" at -35.636,-60.706 h1.52
M18 Embedded Assembly:
  text ".Layer_Name" at -35.636,-60.706 h1.52
M19 Embedded Keepout:
  text ".Layer_Name" at -35.636,-60.706 h1.52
